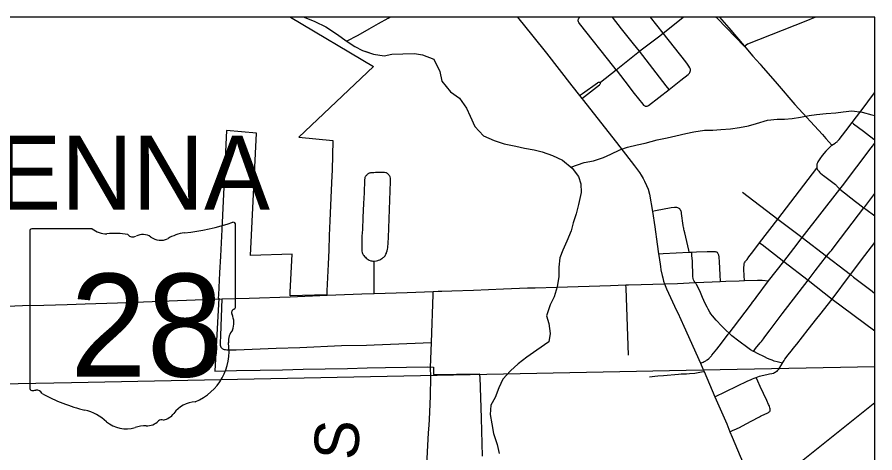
# Model space of a CAD drawing. Extents: x 0 to 1052, y -194 to 246.
# Drawn here: x 7.683 to 8.782, y 20.448 to 21.005 of the extents above; entities that cross this region are included whole.
import ezdxf

# ---------------------------------------------------------------- set-up
doc = ezdxf.new("R2010")
doc.units = 0
for name, color, linetype in [('GM_X_City_Street', 7, 'Continuous'), ('GM_X_Corporation', 7, 'Continuous'), ('GM_X_Corporation_Text', 7, 'Continuous'), ('GM_X_County_Road', 7, 'Continuous'), ('GM_X_Major_River', 7, 'Continuous'), ('GM_X_Minor_River', 7, 'Continuous'), ('GM_X_Rail_Line', 7, 'Continuous'), ('GM_X_State_Location', 7, 'Continuous'), ('GM_X_State_Route', 7, 'Continuous'), ('GM_X_State_Shield', 7, 'Continuous'), ('GM_X_Township_Road', 7, 'Continuous'), ('GM_X_Township_Road_Text', 7, 'Continuous')]:
    doc.layers.add(name, color=color, linetype=linetype)

msp = doc.modelspace()

# ---------------------------------------------------------------- linework, layer by layer
at = {"layer": 'GM_X_City_Street'}
for points in [[(8.4505, 20.938), (8.4476, 20.9417), (8.4035, 20.9975), (8.4028, 20.9987), (8.4024, 20.9996), (8.4021, 21.0007), (8.4021, 21.0021), (8.4024, 21.0031), (8.4029, 21.0041), (8.4042, 21.0055)], [(8.4305, 20.922), (8.4505, 20.938), (8.4719, 20.9552), (8.4804, 20.9617), (8.4812, 20.9624), (8.5049, 20.9804), (8.5109, 20.9848), (8.5254, 20.9965), (8.5365, 21.0054), (8.5366, 21.0055)], [(8.5184, 20.9129), (8.5147, 20.9176), (8.4804, 20.9617), (8.4729, 20.9712), (8.4575, 20.9907), (8.4459, 21.0055)], [(8.4505, 20.938), (8.4617, 20.9236), (8.4738, 20.9079), (8.4848, 20.894), (8.4859, 20.8929), (8.4866, 20.8922), (8.4874, 20.8918), (8.488, 20.8915), (8.4889, 20.8913), (8.4903, 20.8914), (8.4914, 20.8919), (8.4922, 20.8925), (8.5184, 20.9129), (8.5337, 20.9248), (8.5428, 20.9321), (8.5436, 20.9328), (8.5446, 20.9337), (8.5453, 20.9347), (8.5457, 20.9357), (8.546, 20.9373), (8.5458, 20.9389), (8.5452, 20.9404), (8.544, 20.9425), (8.5419, 20.9453), (8.5398, 20.9482), (8.5109, 20.9848), (8.4945, 21.0055)], [(8.4039, 20.905), (8.4077, 20.9078), (8.4266, 20.9215), (8.4272, 20.9218), (8.428, 20.9221), (8.429, 20.9222), (8.4305, 20.922)], [(8.4069, 20.9012), (8.4103, 20.9039), (8.4293, 20.9187), (8.4299, 20.9193), (8.4302, 20.9199), (8.4305, 20.9206), (8.4305, 20.922)], [(8.727, 20.8416), (8.7314, 20.8442), (8.7323, 20.8448), (8.733, 20.8453), (8.7338, 20.846), (8.7345, 20.8467), (8.7364, 20.849), (8.7448, 20.8601), (8.753, 20.8704), (8.7697, 20.8924), (8.7732, 20.897), (8.7806, 20.9069), (8.7822, 20.9089)], [(8.753, 20.8704), (8.7549, 20.8689), (8.7676, 20.8596), (8.7715, 20.8566), (8.7808, 20.8493), (8.7822, 20.8483)], [(8.1405, 20.6515), (8.1405, 20.6543), (8.1406, 20.6928), (8.1436, 20.6933), (8.1454, 20.6938), (8.1463, 20.6941), (8.1478, 20.6948), (8.1492, 20.6955), (8.1505, 20.6963), (8.1513, 20.6969), (8.1522, 20.6976), (8.153, 20.6983), (8.1537, 20.699), (8.1545, 20.7), (8.1552, 20.701), (8.1556, 20.7019), (8.1562, 20.7032), (8.1565, 20.7041), (8.1572, 20.7064), (8.1576, 20.7082), (8.1579, 20.7099), (8.1583, 20.7126), (8.1585, 20.7144), (8.1586, 20.7166), (8.1589, 20.7233), (8.1615, 20.7948), (8.1615, 20.7958), (8.1616, 20.7968), (8.1615, 20.7977), (8.1614, 20.7992), (8.161, 20.8009), (8.1607, 20.8018), (8.1604, 20.8023), (8.16, 20.8029), (8.1595, 20.8035), (8.159, 20.804), (8.1581, 20.8048), (8.1575, 20.8053), (8.1568, 20.8057), (8.1562, 20.806), (8.1555, 20.8062), (8.1538, 20.8064), (8.1516, 20.8065), (8.144, 20.8064), (8.1425, 20.8064), (8.1402, 20.8063), (8.1386, 20.8062), (8.1375, 20.8062), (8.1364, 20.806), (8.1357, 20.8059), (8.1349, 20.8058), (8.1342, 20.8055), (8.1335, 20.8052), (8.1328, 20.8048), (8.132, 20.8042), (8.1312, 20.8035), (8.1306, 20.8029), (8.1301, 20.8023), (8.1295, 20.8015), (8.1292, 20.8009), (8.1288, 20.8001), (8.1286, 20.7993), (8.1285, 20.7984), (8.1284, 20.7977), (8.1283, 20.7966), (8.1277, 20.7806), (8.127, 20.767), (8.1262, 20.749), (8.1256, 20.7335), (8.125, 20.7248), (8.1249, 20.7211), (8.1247, 20.7101), (8.1248, 20.7075), (8.125, 20.7056), (8.1254, 20.704), (8.1258, 20.7027), (8.1266, 20.7012), (8.1272, 20.7002), (8.1283, 20.6989), (8.1293, 20.698), (8.1304, 20.697), (8.1318, 20.6959), (8.133, 20.6951), (8.1344, 20.6943), (8.1362, 20.6936), (8.1374, 20.6933), (8.1388, 20.693), (8.1406, 20.6928)], [(8.6151, 20.6682), (8.6148, 20.6744), (8.6144, 20.6828), (8.6144, 20.6843), (8.6144, 20.6854), (8.6145, 20.6876), (8.6147, 20.6888), (8.6149, 20.6899), (8.6153, 20.6909), (8.6159, 20.692), (8.6166, 20.693), (8.6172, 20.6938), (8.6184, 20.6953), (8.6209, 20.6984), (8.6259, 20.7049), (8.6345, 20.7166), (8.658, 20.7467), (8.708, 20.8121)], [(8.6124, 20.7814), (8.658, 20.7467), (8.6868, 20.7251), (8.6892, 20.7233), (8.7202, 20.6995), (8.7438, 20.6813), (8.7509, 20.6757), (8.755, 20.6725), (8.7786, 20.6544), (8.7822, 20.6517)], [(8.7682, 20.7613), (8.7693, 20.7627), (8.7822, 20.7796)], [(8.5442, 20.7044), (8.5436, 20.7072), (8.5385, 20.7293), (8.5378, 20.7324), (8.5375, 20.7338), (8.5373, 20.7351), (8.5371, 20.7362), (8.5367, 20.7386), (8.5345, 20.7541), (8.5342, 20.7557), (8.534, 20.7567), (8.5336, 20.7578), (8.5329, 20.7589), (8.5321, 20.7598), (8.5313, 20.7605), (8.5306, 20.7608), (8.5296, 20.7613), (8.5284, 20.7616), (8.5273, 20.7618), (8.5253, 20.7619), (8.5211, 20.7612), (8.5009, 20.7573), (8.4974, 20.7566)], [(8.6265, 20.5775), (8.6294, 20.5811), (8.6352, 20.5882), (8.6368, 20.5902), (8.6395, 20.5937), (8.6412, 20.596), (8.648, 20.6051), (8.6636, 20.6255), (8.6969, 20.6688), (8.7059, 20.6806), (8.7202, 20.6995), (8.7227, 20.7022), (8.7251, 20.7048), (8.7265, 20.7066), (8.7314, 20.7131), (8.7682, 20.7613)], [(8.5773, 20.5194), (8.6195, 20.5397), (8.6229, 20.5412), (8.6255, 20.5424), (8.6277, 20.5433), (8.6302, 20.5442), (8.6345, 20.5457), (8.6377, 20.5465), (8.6439, 20.5479), (8.6471, 20.5486), (8.65, 20.5491), (8.6521, 20.5497), (8.6536, 20.5503), (8.6546, 20.5508), (8.6559, 20.5516), (8.6568, 20.5523), (8.6578, 20.5533), (8.659, 20.5547), (8.6604, 20.5568), (8.6617, 20.5589), (8.6637, 20.5623), (8.6644, 20.5633), (8.6658, 20.5657), (8.667, 20.5675), (8.6685, 20.5696), (8.6708, 20.5725), (8.6733, 20.5757), (8.6797, 20.5836), (8.6822, 20.5868), (8.6968, 20.6055), (8.7079, 20.6194), (8.7117, 20.6243), (8.7273, 20.6444), (8.7509, 20.6757), (8.7693, 20.7002), (8.7822, 20.7171)], [(8.6345, 20.7166), (8.6377, 20.7142), (8.6655, 20.6926), (8.6969, 20.6688), (8.7273, 20.6444), (8.7822, 20.6039)], [(8.5049, 20.7023), (8.5109, 20.7026), (8.5442, 20.7044), (8.5475, 20.7045), (8.5538, 20.7049), (8.5674, 20.7055), (8.5761, 20.7055), (8.5774, 20.7054), (8.5783, 20.7051), (8.5792, 20.7048), (8.58, 20.7043), (8.5806, 20.7037), (8.581, 20.7029), (8.5815, 20.7021), (8.5818, 20.7012), (8.582, 20.7003), (8.5822, 20.6992), (8.5824, 20.6979), (8.5826, 20.6922), (8.5834, 20.6756), (8.5838, 20.667)], [(8.6637, 20.5623), (8.6568, 20.5641), (8.6532, 20.565), (8.6506, 20.566), (8.648, 20.567), (8.6445, 20.5685), (8.6406, 20.5703), (8.6317, 20.5747), (8.628, 20.5767), (8.6265, 20.5775), (8.6229, 20.5795), (8.6193, 20.5818), (8.6078, 20.5904), (8.5991, 20.5975), (8.5953, 20.6009), (8.5917, 20.6041), (8.586, 20.6097), (8.5788, 20.6174), (8.574, 20.6231), (8.5722, 20.6255), (8.5707, 20.6276), (8.5684, 20.6314), (8.5671, 20.6341), (8.5649, 20.6386), (8.5613, 20.6466), (8.5586, 20.6529), (8.5553, 20.6602), (8.5538, 20.663), (8.5527, 20.6646), (8.552, 20.6655), (8.5505, 20.6674), (8.5498, 20.6691), (8.5494, 20.6709), (8.5491, 20.6734), (8.5483, 20.6932), (8.5478, 20.6998), (8.5475, 20.7045)], [(8.4664, 20.5727), (8.4634, 20.6584), (8.4632, 20.6625)], [(8.5586, 20.5625), (8.5621, 20.5638), (8.5633, 20.5643), (8.564, 20.5647), (8.5647, 20.565), (8.5657, 20.5655), (8.5666, 20.5661), (8.5672, 20.5665), (8.5689, 20.5678), (8.5697, 20.5685), (8.5705, 20.5692), (8.5713, 20.5701), (8.5721, 20.5709), (8.5729, 20.5719), (8.5734, 20.5724), (8.5796, 20.5805), (8.5855, 20.5881), (8.5943, 20.5996), (8.5953, 20.6009), (8.601, 20.6082), (8.624, 20.6382), (8.6256, 20.6404), (8.6279, 20.6435), (8.6302, 20.6466), (8.6461, 20.6679)], [(7.9456, 20.6446), (7.9436, 20.5977), (7.9432, 20.5883), (7.9432, 20.5866), (7.9433, 20.5853), (7.9436, 20.5841), (7.9442, 20.5828), (7.9448, 20.5821), (7.9454, 20.5814), (7.9459, 20.5811), (7.9466, 20.5807), (7.9472, 20.5804), (7.9483, 20.58), (7.9493, 20.5798), (7.9503, 20.5797), (7.9517, 20.5796), (7.9544, 20.5795), (7.9574, 20.5794), (7.9636, 20.5796), (8.0151, 20.5816), (8.0455, 20.5826), (8.0989, 20.5848), (8.1307, 20.5856), (8.1408, 20.5859), (8.2141, 20.5887)], [(8.4935, 20.5448), (8.4968, 20.5453), (8.5002, 20.5457), (8.5039, 20.546), (8.5113, 20.5466), (8.5304, 20.5483), (8.534, 20.5485), (8.5366, 20.5486), (8.5407, 20.5489), (8.5446, 20.5491), (8.5517, 20.5497), (8.5601, 20.5511), (8.5633, 20.5516)], [(8.5965, 20.4746), (8.6008, 20.4764), (8.602, 20.4769), (8.6087, 20.4801), (8.6125, 20.4821), (8.6235, 20.4879), (8.6345, 20.4938), (8.6356, 20.4944), (8.6366, 20.4949), (8.645, 20.4989), (8.6457, 20.4992), (8.6469, 20.5), (8.6475, 20.5006), (8.6479, 20.5013), (8.6481, 20.5025), (8.648, 20.5037), (8.6476, 20.5052), (8.6472, 20.5067), (8.6467, 20.508), (8.6461, 20.5096), (8.6436, 20.5146), (8.635, 20.5326), (8.6322, 20.5394), (8.6302, 20.5442)]]:
    msp.add_lwpolyline(points, dxfattribs=at)
at = {"layer": 'GM_X_Corporation'}
for points in [[(5.1788, 17.6981), (5.491, 17.9457), (6.1888, 18.4644), (6.5994, 18.7694), (6.8785, 18.9763), (8.1871, 19.9814), (8.6571, 20.341), (8.7822, 20.435), (8.7822, 21.0055), (1.9822, 21.0055), (1.9822, 14.2055)], [(8.6327, 20.3925), (8.7822, 20.512), (8.7822, 21.0055), (8.7062, 21.0055), (8.6936, 21.0005), (8.6188, 20.9709), (8.6153, 20.9679), (8.5799, 21.004), (8.5786, 21.0055), (8.0332, 21.0055), (8.1399, 20.9424), (8.0442, 20.8517), (8.0876, 20.8477), (8.0866, 20.8097), (8.0863, 20.8021), (8.0855, 20.7838), (8.0847, 20.7643), (8.0839, 20.7446), (8.0831, 20.726), (8.0823, 20.707), (8.0815, 20.6891), (8.0801, 20.655), (8.0799, 20.65), (8.0328, 20.6485), (8.0331, 20.6533), (8.0356, 20.7019), (7.982, 20.7004), (7.9897, 20.8568), (7.9515, 20.8604), (7.9452, 20.7335), (7.9435, 20.6994), (7.9424, 20.6782), (7.9411, 20.65), (7.9408, 20.6454), (7.9415, 20.6454), (7.9366, 20.5523), (7.9642, 20.5528), (7.9946, 20.5534), (8.0232, 20.554), (8.0495, 20.5545), (8.078, 20.5551), (8.1064, 20.5557), (8.1316, 20.5562), (8.1552, 20.5566), (8.182, 20.5572), (8.2089, 20.5577), (8.2165, 20.5572), (8.2166, 20.552), (8.2166, 20.5477), (8.2753, 20.5489), (8.2759, 20.5445), (8.2775, 20.4921), (8.2789, 20.4431)]]:
    msp.add_lwpolyline(points, dxfattribs=at)
msp.add_lwpolyline([(8.7822, 20.435), (8.7822, 21.0055), (5.5898, 21.0055), (5.6935, 20.5776), (5.9283, 19.6076), (5.992, 19.3448), (6.152, 18.6129), (6.1888, 18.4644), (6.5994, 18.7694), (6.8785, 18.9763), (8.1871, 19.9814), (8.6571, 20.341)], close=True, dxfattribs=at)
at = {"layer": 'GM_X_County_Road'}
msp.add_lwpolyline([(8.7371, 20.7852), (8.7405, 20.7896), (8.7776, 20.8382), (8.7822, 20.844)], dxfattribs=at)
at = {"layer": 'GM_X_Major_River'}
for points in [[(8.0511, 21.0055), (8.0645, 21.0001), (8.0788, 20.9931), (8.0923, 20.9842), (8.1062, 20.9742), (8.116, 20.968), (8.1258, 20.9629), (8.1398, 20.9582), (8.1534, 20.9561), (8.1633, 20.9579), (8.1773, 20.9585), (8.1921, 20.959), (8.2027, 20.9574), (8.217, 20.9515), (8.2248, 20.9358), (8.2272, 20.9233), (8.2384, 20.9099), (8.2501, 20.9018)], [(8.2501, 20.9018), (8.259, 20.8891), (8.2638, 20.8788), (8.2697, 20.8655), (8.2805, 20.8536), (8.2945, 20.8473), (8.3073, 20.8434), (8.322, 20.8401), (8.3334, 20.8377), (8.3455, 20.8357), (8.3557, 20.8329), (8.3689, 20.8285), (8.3821, 20.8223), (8.3944, 20.8119), (8.4023, 20.8015), (8.4056, 20.792), (8.4058, 20.781), (8.4025, 20.7655), (8.3993, 20.7534), (8.3954, 20.7421), (8.393, 20.7319), (8.3875, 20.7186), (8.3824, 20.7069), (8.3785, 20.6971), (8.3772, 20.6854), (8.3774, 20.6733), (8.3753, 20.66), (8.3714, 20.6475), (8.3663, 20.637), (8.3616, 20.623), (8.3645, 20.6131), (8.3662, 20.6002), (8.3642, 20.5896), (8.3492, 20.5788), (8.3362, 20.5702), (8.3251, 20.5616), (8.3151, 20.5527), (8.3055, 20.5418), (8.3004, 20.5308), (8.2957, 20.5184), (8.2899, 20.5086), (8.2894, 20.4968), (8.2915, 20.4847), (8.2936, 20.4721), (8.298, 20.458), (8.3008, 20.4466)]]:
    msp.add_lwpolyline(points, dxfattribs=at)
at = {"layer": 'GM_X_Minor_River'}
for points in [[(8.1053, 20.9748), (8.1201, 20.9822), (8.1342, 20.9904), (8.146, 20.9975), (8.1586, 21.0043), (8.1607, 21.0055)], [(8.1286, 20.962), (8.1398, 20.9582), (8.1534, 20.9561), (8.1633, 20.9579), (8.1773, 20.9585), (8.1921, 20.959), (8.2027, 20.9574), (8.217, 20.9515), (8.2248, 20.9358), (8.2272, 20.9233), (8.2384, 20.9099), (8.2501, 20.9018)], [(8.2501, 20.9018), (8.259, 20.8891), (8.2638, 20.8788), (8.2697, 20.8655), (8.2805, 20.8536), (8.2945, 20.8473), (8.3073, 20.8434), (8.322, 20.8401), (8.3334, 20.8377), (8.3455, 20.8357), (8.3557, 20.8329), (8.3689, 20.8285), (8.3821, 20.8223), (8.3944, 20.8119), (8.4023, 20.8015), (8.4056, 20.792), (8.4058, 20.781), (8.4025, 20.7655), (8.3993, 20.7534), (8.3954, 20.7421), (8.393, 20.7319), (8.3875, 20.7186), (8.3824, 20.7069), (8.3785, 20.6971), (8.3772, 20.6854), (8.3774, 20.6733), (8.3753, 20.66), (8.3714, 20.6475), (8.3663, 20.637), (8.3616, 20.623), (8.3645, 20.6131), (8.3662, 20.6002), (8.3642, 20.5896), (8.3492, 20.5788), (8.3362, 20.5702), (8.3251, 20.5616), (8.3151, 20.5527), (8.3055, 20.5418), (8.3004, 20.5308), (8.2957, 20.5184), (8.2899, 20.5086), (8.2894, 20.4968), (8.2915, 20.4847), (8.2936, 20.4721), (8.298, 20.458), (8.3008, 20.4466)], [(8.3926, 20.8135), (8.4096, 20.8194), (8.4218, 20.8216), (8.4344, 20.8257), (8.4439, 20.8301), (8.4553, 20.8357), (8.4652, 20.8391), (8.4774, 20.842), (8.488, 20.8442), (8.5032, 20.8482), (8.5162, 20.8511), (8.5272, 20.8533), (8.5401, 20.8566), (8.55, 20.8588), (8.5637, 20.8609), (8.5747, 20.8608), (8.585, 20.8615), (8.5971, 20.8625), (8.6089, 20.8643), (8.6203, 20.8665), (8.6306, 20.8691), (8.6446, 20.8735), (8.6572, 20.8749), (8.6666, 20.8748), (8.6761, 20.8755), (8.6868, 20.8773), (8.6978, 20.8795), (8.7073, 20.8809), (8.7198, 20.8823), (8.732, 20.883), (8.7415, 20.8844), (8.7525, 20.8854), (8.7658, 20.8838), (8.7783, 20.8803), (8.7822, 20.8794)]]:
    msp.add_lwpolyline(points, dxfattribs=at)
at = {"layer": 'GM_X_Rail_Line'}
msp.add_lwpolyline([(1.9822, 20.4716), (2.0551, 20.4708), (2.4106, 20.4737), (3.1102, 20.4767), (3.8818, 20.4767), (4.2729, 20.4769), (4.6986, 20.4854), (5.3445, 20.496), (5.674, 20.5018), (6.3876, 20.5117), (6.862, 20.5208), (7.7527, 20.5376), (8.5619, 20.5538), (8.7822, 20.5583)], dxfattribs=at)
at = {"layer": 'GM_X_State_Route'}
for p, q in [((8.4039, 20.905), (8.4069, 20.9012)), ((8.5586, 20.5625), (8.5617, 20.5552))]:
    msp.add_line(p, q, dxfattribs=at)
for points in [[(8.3244, 21.0055), (8.3439, 20.9812), (8.3613, 20.9593), (8.3939, 20.9177), (8.4039, 20.905)], [(8.4069, 20.9012), (8.4088, 20.8987), (8.4308, 20.8709), (8.4512, 20.8451), (8.4555, 20.8396)], [(8.4555, 20.8396), (8.4743, 20.8152), (8.4768, 20.8118), (8.4806, 20.8064), (8.4827, 20.8031), (8.4852, 20.799), (8.4871, 20.7955), (8.4897, 20.7899), (8.4915, 20.7852), (8.4932, 20.7786), (8.4974, 20.7566)], [(8.6461, 20.6679), (8.6655, 20.6926), (8.6785, 20.7094), (8.6892, 20.7233), (8.7371, 20.7852)], [(8.7371, 20.7852), (8.7574, 20.7694), (8.7682, 20.7613), (8.7708, 20.7594), (8.7822, 20.7509)], [(8.4974, 20.7566), (8.5004, 20.7369), (8.5033, 20.7147), (8.5049, 20.7023)], [(8.5049, 20.7023), (8.5056, 20.6975), (8.5073, 20.686), (8.5081, 20.6817), (8.5095, 20.6748), (8.5103, 20.6716), (8.5115, 20.6674), (8.5125, 20.664)], [(8.3471, 20.659), (8.3747, 20.6599), (8.4436, 20.662), (8.4632, 20.6625), (8.4666, 20.6625), (8.4827, 20.6631), (8.5125, 20.664)], [(8.5125, 20.664), (8.5293, 20.6645), (8.552, 20.6655), (8.5528, 20.6655), (8.5838, 20.667), (8.5913, 20.6673), (8.6082, 20.6679)], [(8.5125, 20.664), (8.5154, 20.6576), (8.5281, 20.6299), (8.5296, 20.6267), (8.5372, 20.6098), (8.5586, 20.5625)], [(8.6082, 20.6679), (8.6151, 20.6682), (8.632, 20.6688), (8.6335, 20.6688), (8.6379, 20.6686), (8.6461, 20.6679)], [(7.9456, 20.6446), (7.9804, 20.6457), (8.0329, 20.6475), (8.0804, 20.6494), (8.1246, 20.651), (8.1405, 20.6515), (8.183, 20.653), (8.2163, 20.6542), (8.2227, 20.6544), (8.2275, 20.6546)], [(8.2275, 20.6546), (8.2401, 20.6551), (8.268, 20.6558), (8.3064, 20.6575), (8.3369, 20.6587), (8.3471, 20.659)], [(7.6504, 20.6346), (7.6901, 20.6361), (7.7174, 20.6368), (7.7472, 20.6376), (7.7702, 20.6384), (7.8118, 20.6398), (7.856, 20.6415), (7.8886, 20.6426), (7.9456, 20.6446)], [(8.5617, 20.5552), (8.5633, 20.5516), (8.5773, 20.5194), (8.5924, 20.4845), (8.5952, 20.4777), (8.5965, 20.4746), (8.5993, 20.4677), (8.6097, 20.4434), (8.6185, 20.4234), (8.6224, 20.4143), (8.6332, 20.3906)]]:
    msp.add_lwpolyline(points, dxfattribs=at)
at = {"layer": 'GM_X_State_Shield'}
for p, q in [((7.963, 20.6348), (7.963, 20.7395)), ((7.6994, 20.7311), (7.6994, 20.531)), ((7.7792, 20.7345), (7.702, 20.7345)), ((7.963, 20.6348), (7.963, 20.6348))]:
    msp.add_line(p, q, dxfattribs=at)
for centre, radius, start, end in [((7.8691, 21.0073), 0.2796, 275.8445, 288.9065), ((7.9601, 20.7399), 0.00294, 351.8621, 97.738), ((7.7024, 20.7315), 0.00305, 98.1301, 188.1301), ((7.7976, 20.7577), 0.0296, 231.6195, 271.1119), ((7.8074, 20.6222), 0.1064, 80.4867, 94.9883), ((7.9048, 20.6734), 0.0563, 97.3462, 120.7689), ((7.8315, 20.7325), 0.00855, 219.7921, 297.1024), ((7.8441, 20.7094), 0.0178, 54.4667, 119.1411), ((7.867, 20.7411), 0.0214, 233.8562, 294.8282), ((7.9624, 20.6271), 0.00454, 107.944, 210.337), ((7.9599, 20.6344), 0.00314, 289.6038, 7.7341), ((7.9335, 20.6139), 0.0273, 340.033, 23.6496), ((7.9736, 20.591), 0.0198, 136.8065, 186.9296), ((7.8848, 20.5777), 0.0699, 292.3089, 8.9858), ((7.7024, 20.5305), 0.00308, 171.9584, 258.3066), ((7.7029, 20.551), 0.0235, 267.339, 280.6039), ((7.7077, 20.5194), 0.00848, 29.7484, 93.2717), ((7.8148, 20.6992), 0.2019, 240.4129, 257.1985), ((7.9143, 20.4748), 0.0383, 94.4031, 142.5768), ((7.7546, 20.441), 0.0632, 47.1842, 75.836), ((7.8657, 20.5116), 0.0226, 282.8732, 323.2771), ((7.8229, 20.5184), 0.0401, 230.7004, 286.2918), ((7.849, 20.5034), 0.0214, 268.777, 315.5493), ((7.8683, 20.484), 0.00601, 65.7517, 132.6484), ((7.8461, 20.4492), 0.0329, 85.6951, 111.2099)]:
    msp.add_arc(centre, radius, start, end, dxfattribs=at)
at = {"layer": 'GM_X_Township_Road'}
for p, q in [((8.2129, 20.5569), (8.2141, 20.5887)), ((8.2131, 20.545), (8.2129, 20.5569))]:
    msp.add_line(p, q, dxfattribs=at)
for points in [[(8.5831, 21.0055), (8.5951, 20.9916), (8.6147, 20.9687)], [(8.6147, 20.9687), (8.626, 20.9556), (8.635, 20.9454), (8.6365, 20.9435), (8.6568, 20.9201), (8.6796, 20.8938), (8.7149, 20.855), (8.7193, 20.8501), (8.727, 20.8416)], [(8.727, 20.8416), (8.7194, 20.8338), (8.7147, 20.8281), (8.7116, 20.824), (8.7099, 20.8215), (8.7091, 20.82), (8.7086, 20.8187), (8.708, 20.817), (8.7078, 20.816), (8.7078, 20.8153), (8.7078, 20.814), (8.708, 20.8121)], [(8.708, 20.8121), (8.7087, 20.8105), (8.7092, 20.8095), (8.7102, 20.8081), (8.7113, 20.8069), (8.712, 20.8062), (8.7149, 20.8036), (8.7163, 20.8025), (8.7316, 20.7911), (8.7329, 20.7899), (8.7336, 20.7891), (8.7371, 20.7852)], [(8.2141, 20.5887), (8.2162, 20.6503), (8.2163, 20.6542)], [(8.2067, 20.4065), (8.2067, 20.4075), (8.2099, 20.465), (8.2104, 20.4731), (8.2109, 20.483), (8.2113, 20.4901), (8.2118, 20.4999), (8.2126, 20.5203), (8.2131, 20.545)]]:
    msp.add_lwpolyline(points, dxfattribs=at)

# ---------------------------------------------------------------- texts
at = {"layer": 'GM_X_Corporation_Text'}
msp.add_text('NEW VIENNA', height=0.0947, rotation=0, dxfattribs=at).set_placement((7.205, 20.7588))
at = {"layer": 'GM_X_State_Location'}
for s in ['s', 'r']:
    msp.add_text(s, height=0.000189, dxfattribs=at).set_placement((7.8282, 20.6177))
msp.add_text('28', height=0.000189, rotation=0, dxfattribs=at).set_placement((7.7805, 20.6039))
at = {"layer": 'GM_X_State_Shield'}
msp.add_text('28', height=0.13184, dxfattribs=at).set_placement((7.7511, 20.5451))
at = {"layer": 'GM_X_Township_Road_Text'}
msp.add_text('PHILLIPS', height=0.05682, rotation=87.4332, dxfattribs=at).set_placement((8.1073, 20.155))

doc.saveas('drawing.dxf')
